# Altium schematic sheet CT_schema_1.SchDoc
size 662 x 632 mm
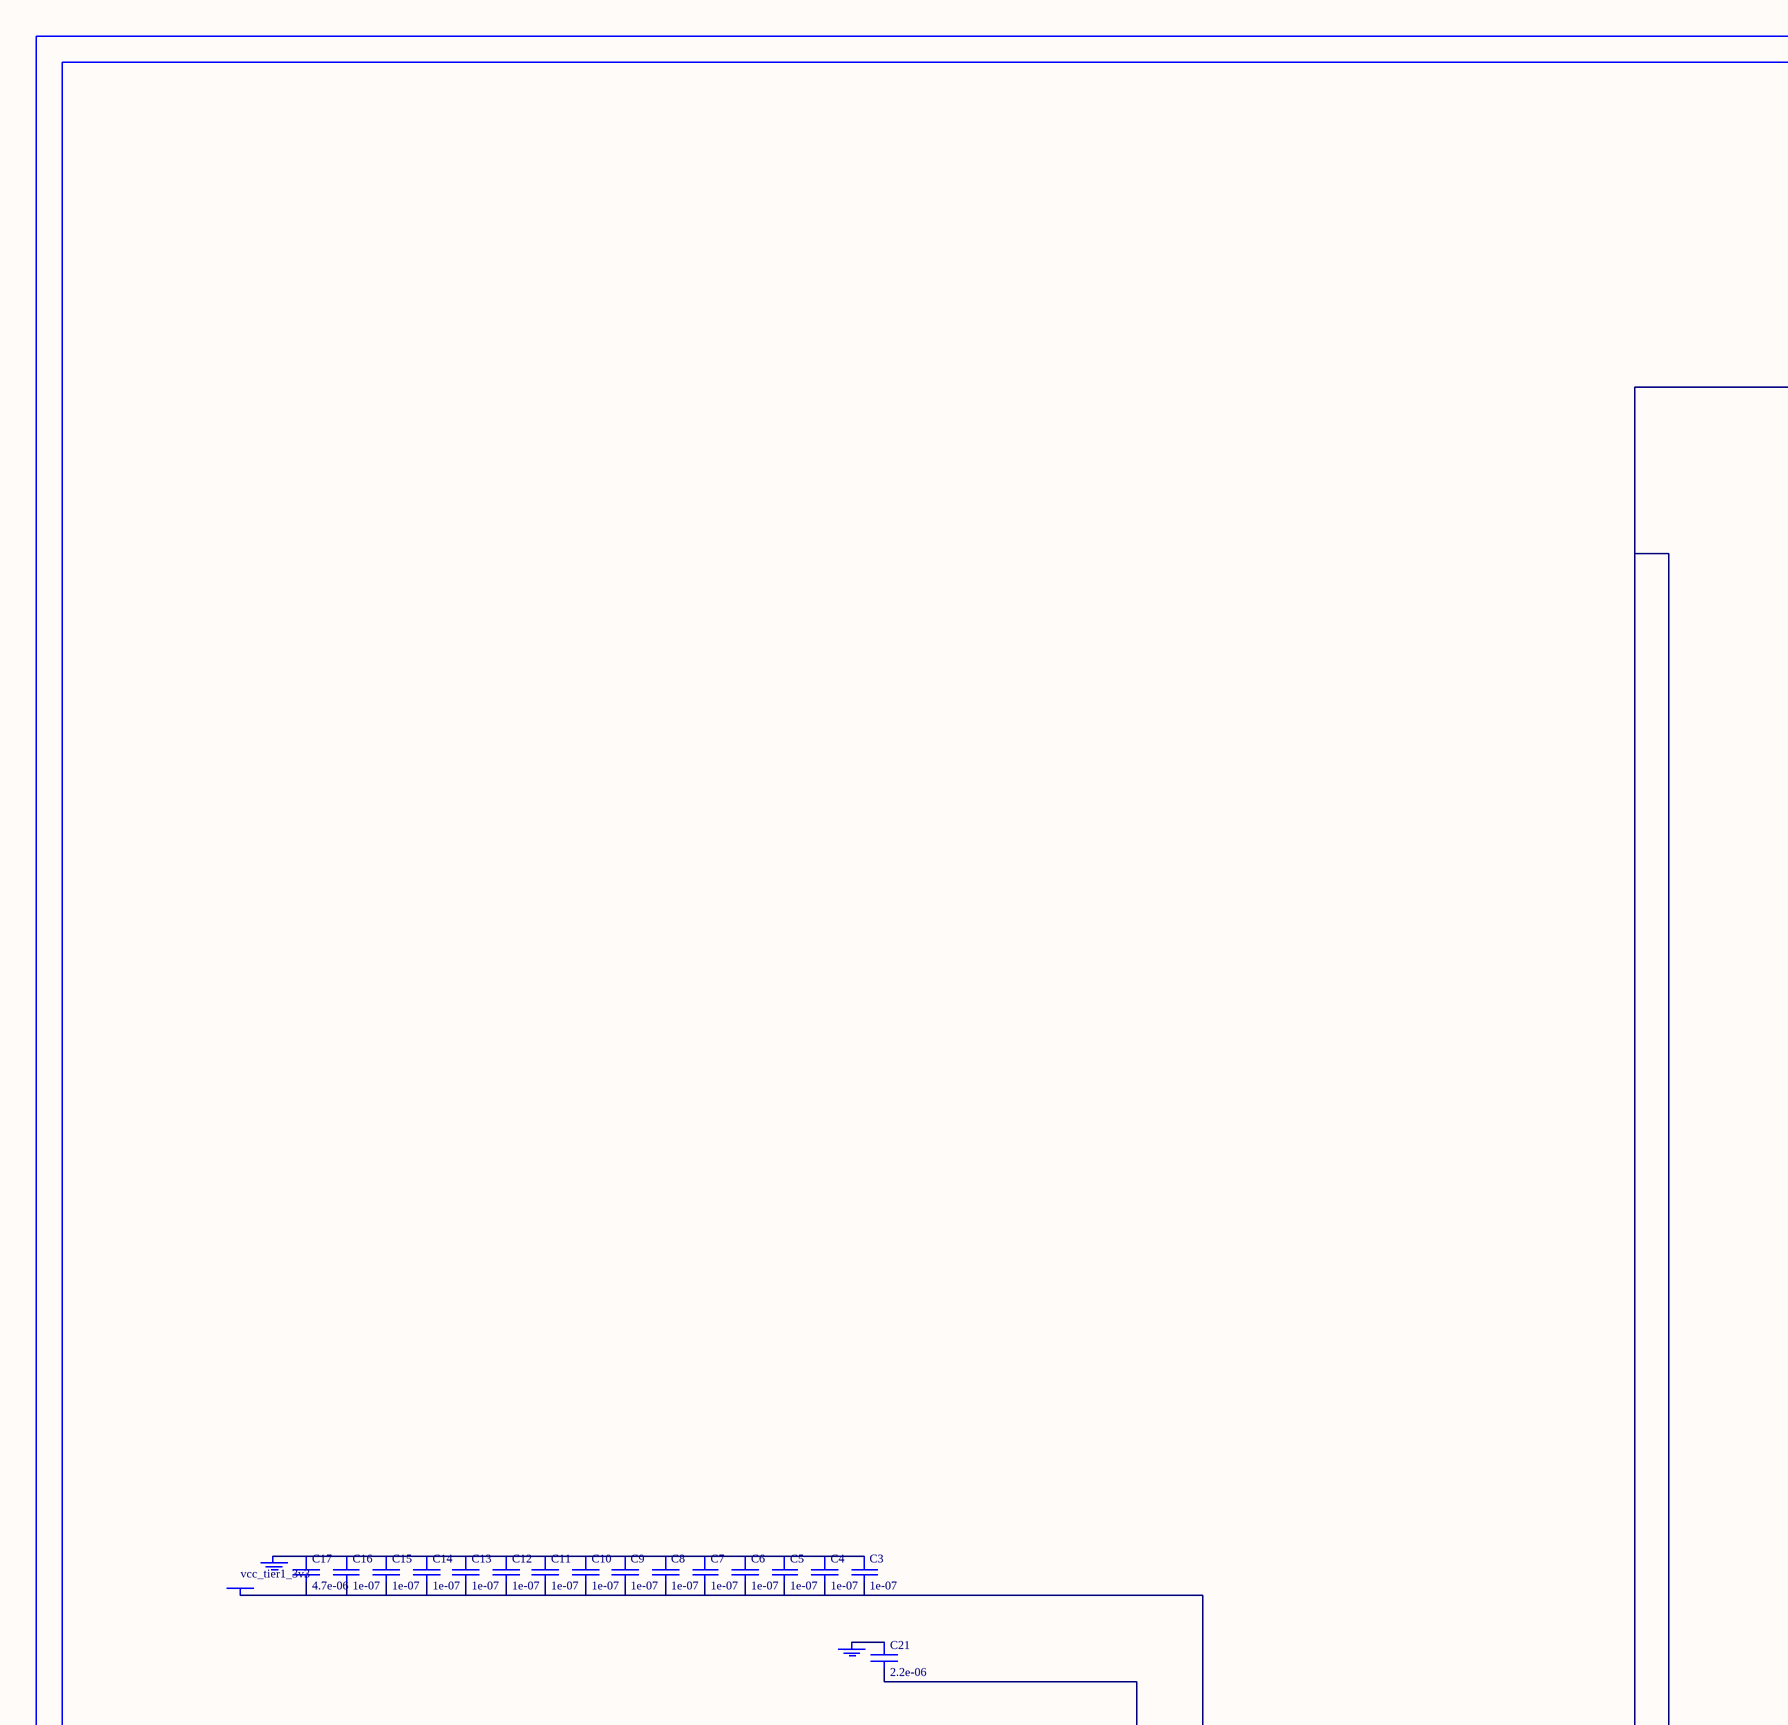
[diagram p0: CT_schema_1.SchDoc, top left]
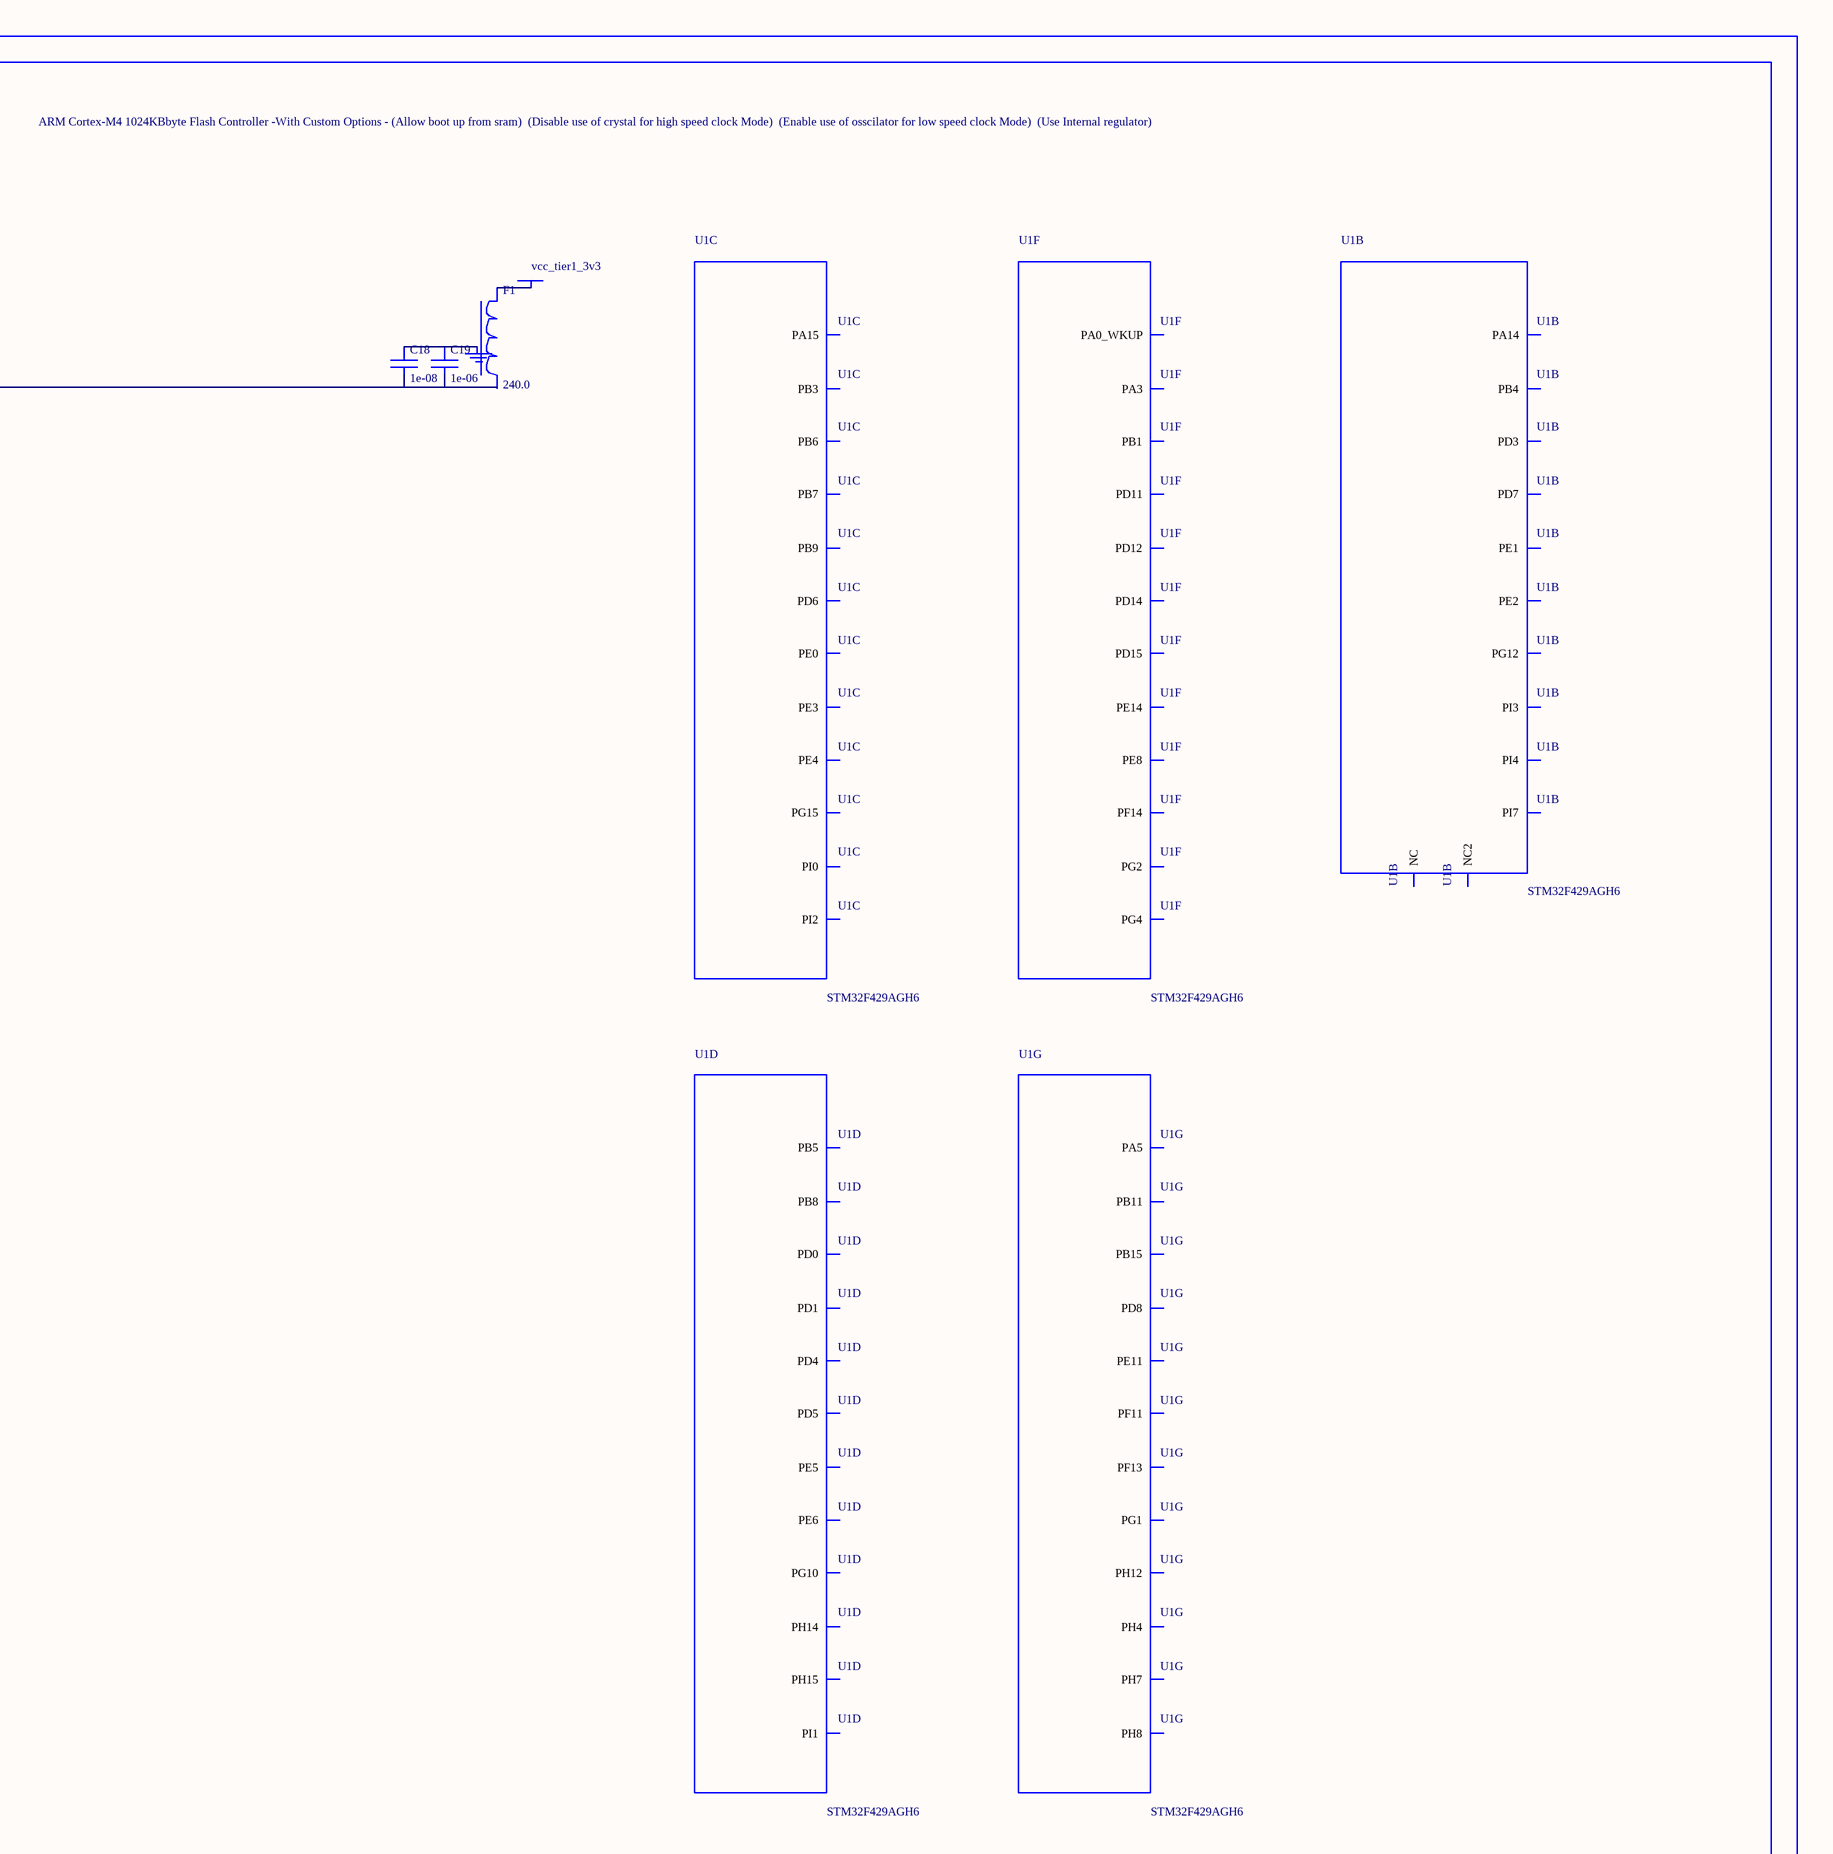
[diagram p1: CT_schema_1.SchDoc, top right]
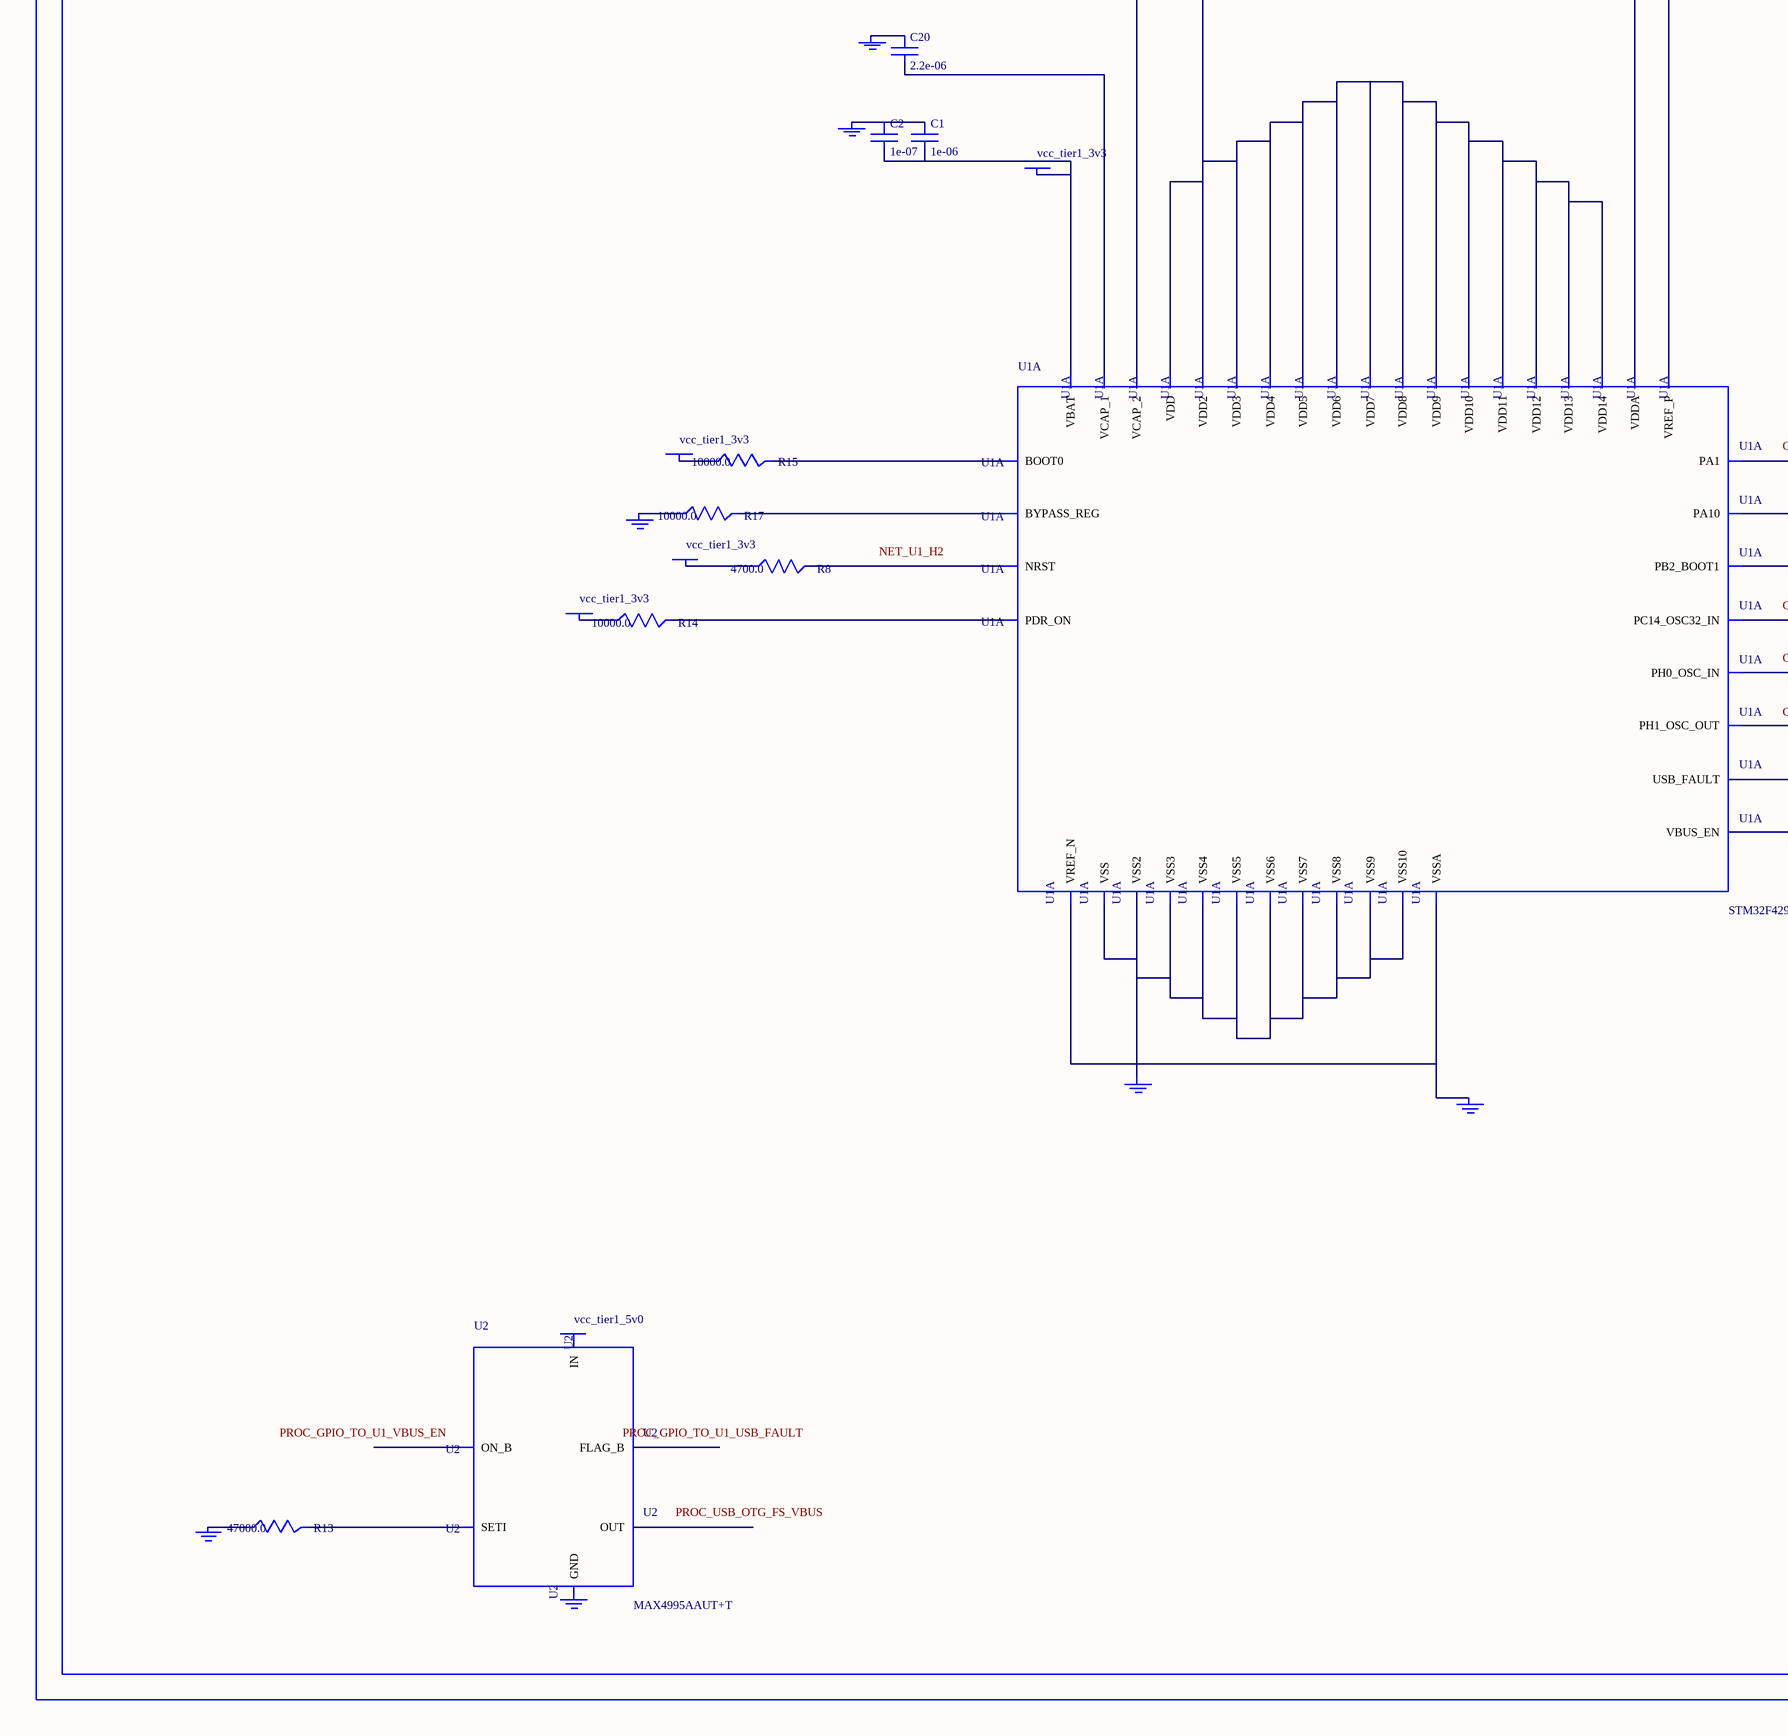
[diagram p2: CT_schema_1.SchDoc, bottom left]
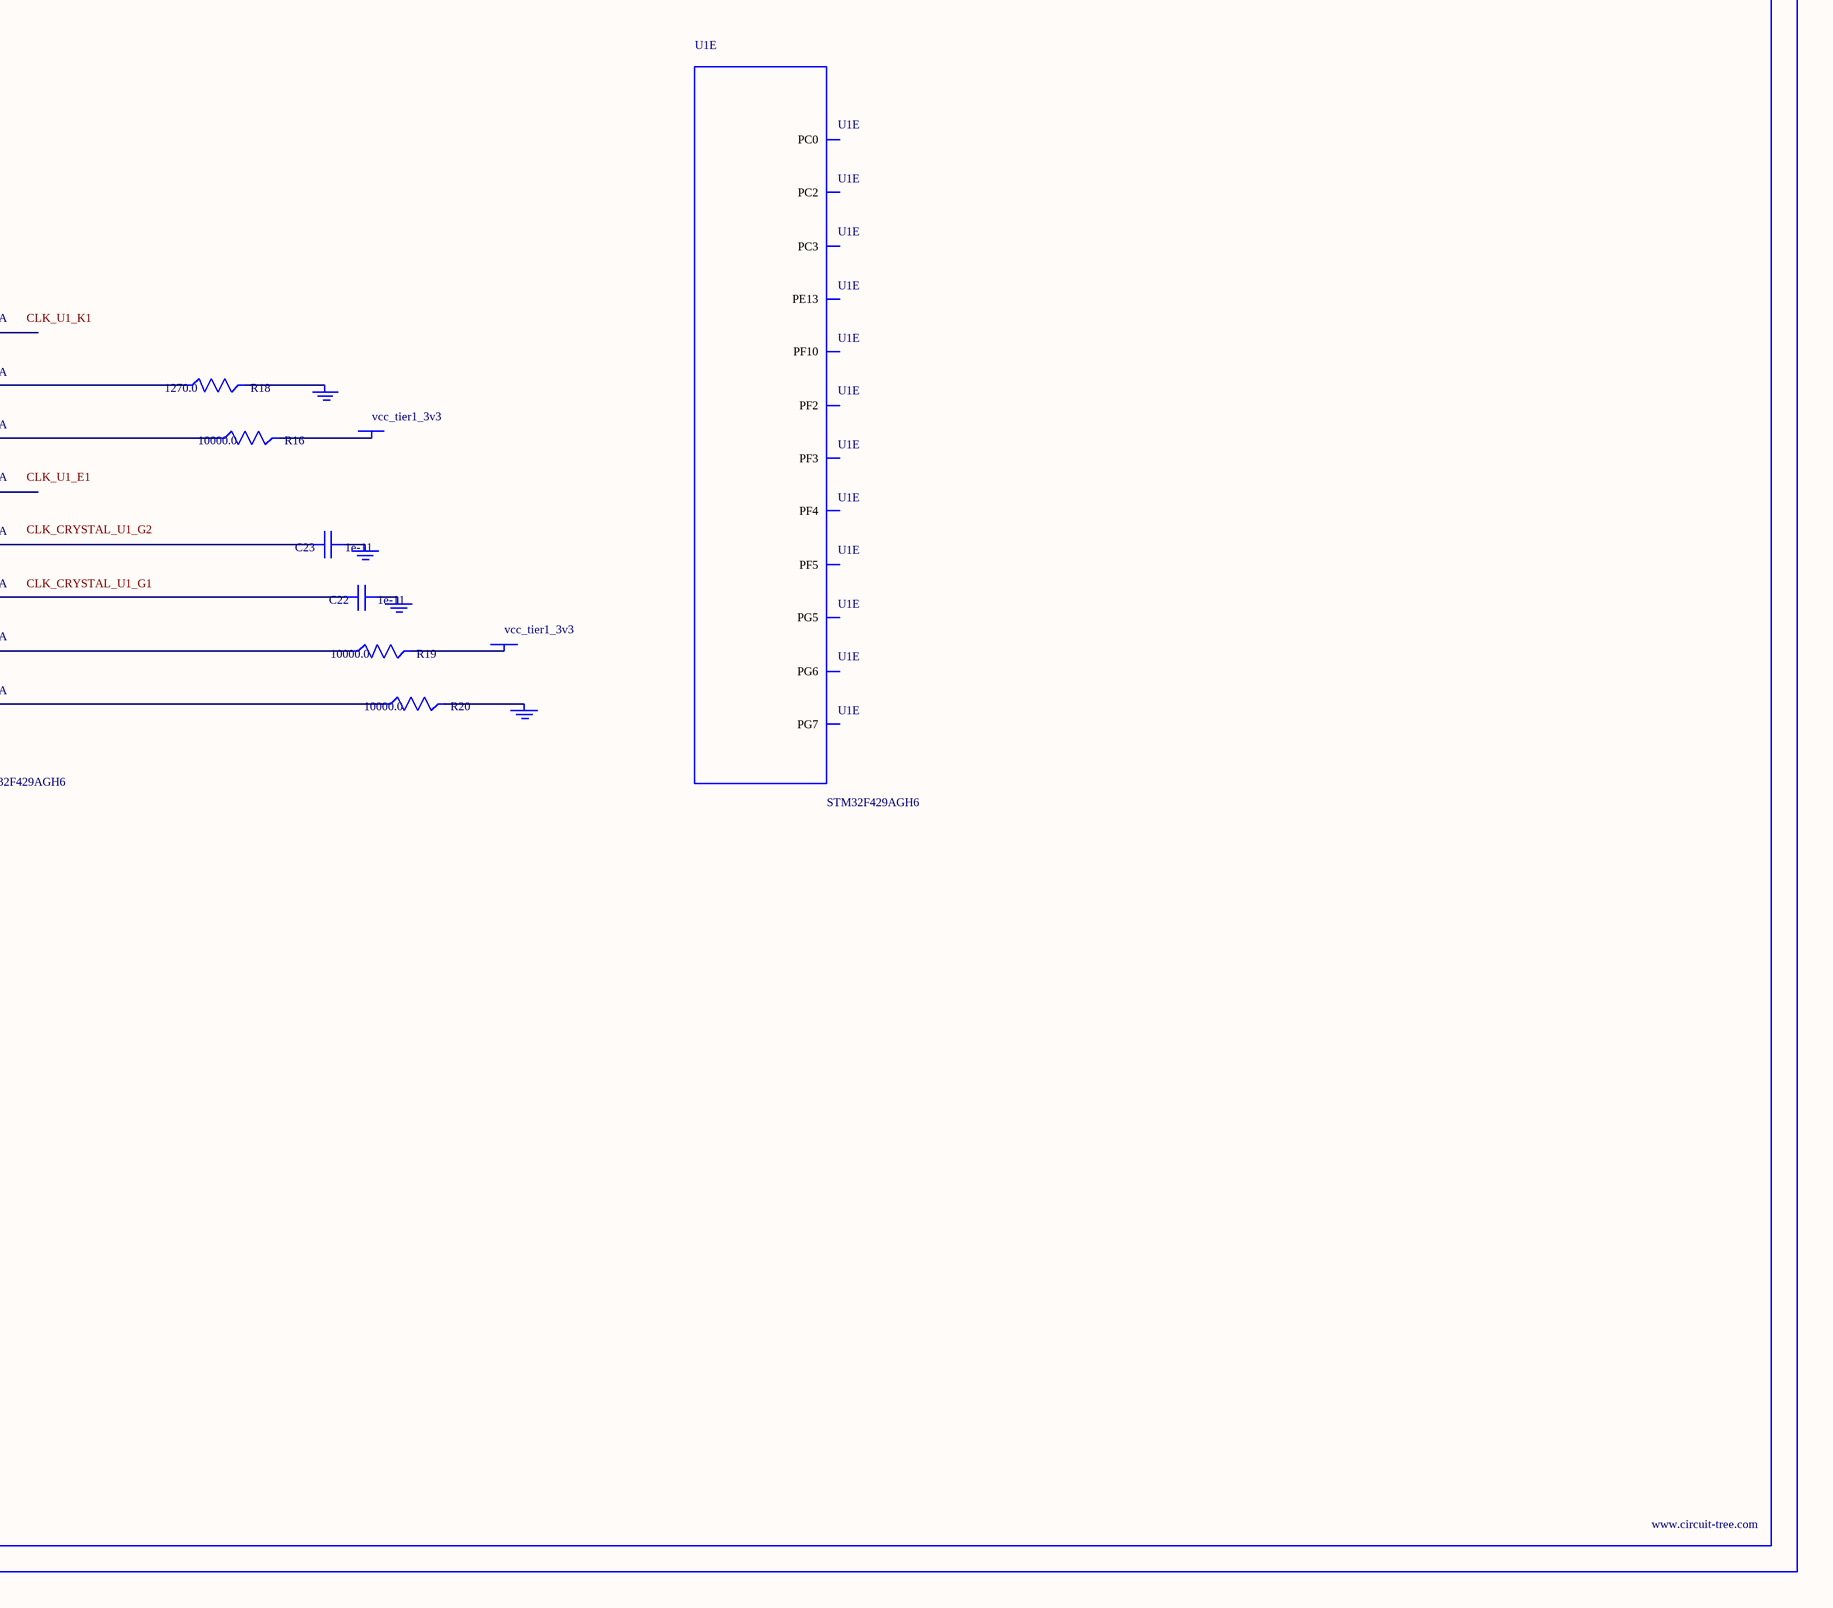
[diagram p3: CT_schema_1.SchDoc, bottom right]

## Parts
BORDER0  (no value)
C1  1e-06  [C0603]
C2  1e-07  [C0603]
C3  1e-07  [C0603]
C4  1e-07  [C0603]
C5  1e-07  [C0603]
C6  1e-07  [C0603]
C7  1e-07  [C0603]
C8  1e-07  [C0603]
C9  1e-07  [C0603]
C10  1e-07  [C0603]
C11  1e-07  [C0603]
C12  1e-07  [C0603]
C13  1e-07  [C0603]
C14  1e-07  [C0603]
C15  1e-07  [C0603]
C16  1e-07  [C0603]
C17  4.7e-06  [C0603]
C18  1e-08  [C0603]
C19  1e-06  [C0603]
C20  2.2e-06  [C0603]
C21  2.2e-06  [C0603]
C22  1e-11  [C0402]
C23  1e-11  [C0402]
F1  240.0  [L0603]
GND_INSTANCE_0_0  (no value)
GND_INSTANCE_0_1  (no value)
GND_INSTANCE_0_2  (no value)
GND_INSTANCE_0_3  (no value)
GND_INSTANCE_0_4  (no value)
GND_INSTANCE_0_5  (no value)
GND_INSTANCE_0_6  (no value)
GND_INSTANCE_0_7  (no value)
GND_INSTANCE_0_8  (no value)
GND_INSTANCE_0_9  (no value)
GND_INSTANCE_0_10  (no value)
GND_INSTANCE_0_11  (no value)
GND_INSTANCE_0_12  (no value)
GND_INSTANCE_0_13  (no value)
POWER_INSTANCE_0_0  vcc_tier1_3v3
POWER_INSTANCE_0_1  vcc_tier1_3v3
POWER_INSTANCE_0_2  vcc_tier1_3v3
POWER_INSTANCE_0_3  vcc_tier1_3v3
POWER_INSTANCE_0_4  vcc_tier1_3v3
POWER_INSTANCE_0_5  vcc_tier1_3v3
POWER_INSTANCE_0_6  vcc_tier1_3v3
POWER_INSTANCE_0_7  vcc_tier1_3v3
POWER_INSTANCE_0_8  vcc_tier1_5v0
R8  4700.0  [R0603]
R13  47000.0  [R0603]
R14  10000.0  [R0603]
R15  10000.0  [R0603]
R16  10000.0  [R0603]
R17  10000.0  [R0603]
R18  1270.0  [R0603]
R19  10000.0  [R0603]
R20  10000.0  [R0603]
U1  STM32F429AGH6  [UFBGA169]  (parts A,B,C,D,E,F,G of 11)
U2  MAX4995AAUT+T  [SOT-23-6]

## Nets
NetC1_1: C1.1 C2.1 GND_INSTANCE_0_0.0(GND)
NetC1_2: C1.2 C2.2 POWER_INSTANCE_0_0.0(PWR) U1.E5(VBAT)
NetC3_1: C3.1 C4.1 C5.1 C6.1 C7.1 C8.1 C9.1 C10.1 C11.1 C12.1 C13.1 C14.1 C15.1 C16.1 C17.1 GND_INSTANCE_0_2.0(GND)
NetC3_2: C3.2 C4.2 C5.2 C6.2 C7.2 C8.2 C9.2 C10.2 C11.2 C12.2 C13.2 C14.2 C15.2 C16.2 C17.2 POWER_INSTANCE_0_2.0(PWR) U1.D3(VDD2) U1.D6(VDD3) U1.D10(VDD) U1.E6(VDD4) U1.F4(VDD5) U1.F7(VDD6) U1.F8(VDD7) U1.G8(VDD9) U1.G10(VDD8) U1.H4(VDD10) U1.H8(VDD11) U1.J11(VDD12) U1.K6(VDD13) U1.L6(VDD14)
NetC18_1: C18.1 C19.1 GND_INSTANCE_0_1.0(GND)
NetC18_2: C18.2 C19.2 U1.J3(VREF_P) U1.J4(VDDA)
NetC20_1: C20.1 GND_INSTANCE_0_4.0(GND)
NetC20_2: C20.2 U1.N9(VCAP_1)
NetC21_1: C21.1 GND_INSTANCE_0_5.0(GND)
NetC21_2: C21.2 U1.D12(VCAP_2)
NetC22_1: C22.1 GND_INSTANCE_0_6.0(GND)
NetC22_2: C22.2 U1.G1(PH1_OSC_OUT)
NetC23_1: C23.1 GND_INSTANCE_0_7.0(GND)
NetC23_2: C23.2 U1.G2(PH0_OSC_IN)
NetF1_1: F1.1 POWER_INSTANCE_0_1.0(PWR)
NetGND_INSTANCE_0_3_0: GND_INSTANCE_0_3.0(GND) R17.1
NetGND_INSTANCE_0_8_0: GND_INSTANCE_0_8.0(GND) R18.2
NetGND_INSTANCE_0_9_0: GND_INSTANCE_0_9.0(GND) R20.2
NetGND_INSTANCE_0_10_0: GND_INSTANCE_0_10.0(GND) U1.J1(VSSA) U1.J2(VREF_N)
NetGND_INSTANCE_0_11_0: GND_INSTANCE_0_11.0(GND) U1.D7(VSS2) U1.D11(VSS) U1.E7(VSS3) U1.F5(VSS4) U1.F6(VSS5) U1.G7(VSS6) U1.G9(VSS7) U1.J6(VSS9) U1.J7(VSS10) U1.J10(VSS8)
NetGND_INSTANCE_0_12_0: GND_INSTANCE_0_12.0(GND) R13.1
NetPOWER_INSTANCE_0_3_0: POWER_INSTANCE_0_3.0(PWR) R14.1
NetPOWER_INSTANCE_0_4_0: POWER_INSTANCE_0_4.0(PWR) R15.1
NetPOWER_INSTANCE_0_5_0: POWER_INSTANCE_0_5.0(PWR) R16.2
NetPOWER_INSTANCE_0_6_0: POWER_INSTANCE_0_6.0(PWR) R19.2
NetPOWER_INSTANCE_0_7_0: POWER_INSTANCE_0_7.0(PWR) R8.1
NetR8_2: R8.2 U1.H2(NRST)
NetR13_2: R13.2 U2.3(SETI)
NetR14_2: R14.2 U1.C3(PDR_ON)
NetR15_2: R15.2 U1.A5(BOOT0)
NetR16_1: R16.1 U1.L5(PB2_BOOT1)
NetR17_2: R17.2 U1.M1(BYPASS_REG)
NetR18_1: R18.1 U1.E9(PA10)
NetR19_1: R19.1 U1.A3(USB_FAULT)
NetR20_1: R20.1 U1.A2(VBUS_EN)

Not connected (* = marked no-connect by the designer): F1 2; GND_INSTANCE_0_13 0(GND); POWER_INSTANCE_0_8 0(PWR); U1 A1(NC) A4(PE1) A6(PB4) A7(PG12) A8(PD7) A9(PD3) A11(PA14) A12(PI3) A13(NC2) B1(PI7) B2(PE2) B3(PI4) B4(PE0) B5(PB7) B6(PB3) B8(PD6) B11(PA15) B12(PI2) B13(PI0) C1(PE3) C2(PE4) C4(PB9) C5(PB6) C6(PG15) C7(PG10) C8(PD5) C9(PD1) C11(PI1) C12(PH15) C13(PH14) D1(PE5) D2(PE6) D4(PB8) D5(PB5) D8(PD4) D9(PD0) E1(PC14_OSC32_IN) G3(PF4) G4(PF3) G5(PF2) G6(PC0) G11(PG6) G12(PG7) G13(PG5) H1(PF10) H3(PF5) H6(PC2) H7(PC3) H9(PE13) H10(PD11) H11(PD14) H12(PG4) H13(PG2) J5(PA0_WKUP) J8(PE8) J9(PE14) J12(PD15) J13(PD12) K1(PA1) K3(PA3) K5(PB1) K7(PF14) L10(PH8) L11(PH12) L12(PD8) L13(PB15) M2(PH4) M3(PA5) M5(PF11) M6(PF13) M7(PG1) M8(PE11) M9(PB11) M10(PH7); U2 1(OUT) 2(GND) 4(ON_B) 5(IN) 6(FLAG_B)

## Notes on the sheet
- Labels drawn without touching a wire or pin: CLK_CRYSTAL_U1_G1, CLK_CRYSTAL_U1_G2, CLK_U1_E1, CLK_U1_K1, NET_U1_H2, PROC_GPIO_TO_U1_USB_FAULT, PROC_GPIO_TO_U1_VBUS_EN, PROC_USB_OTG_FS_VBUS

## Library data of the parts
BORDER0 = BORDER_PAGE0
C1 C19 = C0603C105K3RACTU
C2-C16 = 06035C104K4Z2A
C17 = GRM188R6YA475KE15D
C18 = 06035C103K4Z2A
C20 C21 = C0603C225K8RACTU
C22 C23 = C0402C100K3GACTU
F1 = Z0603C241ASMST
GND_INSTANCE_0_0-GND_INSTANCE_0_13 = GND
POWER_INSTANCE_0_0-POWER_INSTANCE_0_8 = PWR
R8 = RC0603JR-074K7L
R13 = RC0603JR-0747KL
R14-R17 R19 R20 = RC0603JR-0710KL
R18 = RC0603FR-071K27L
